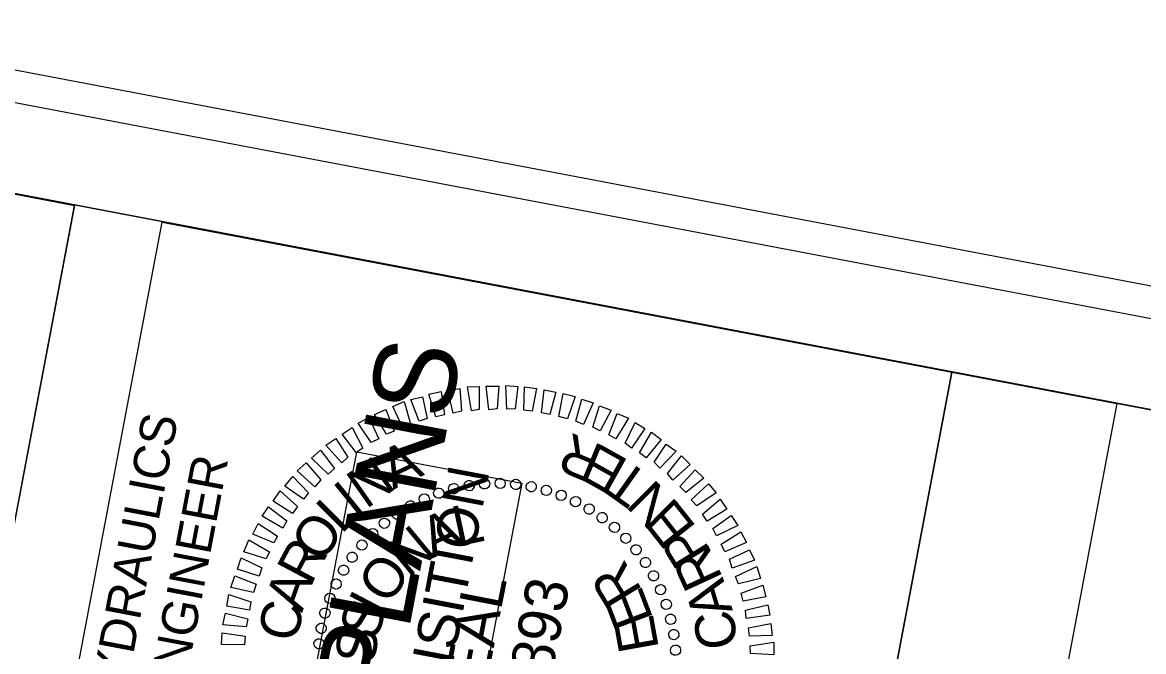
# Model space of a CAD drawing. Extents: x 1615685 to 1617075, y 899072 to 901363.
# Drawn here: x 1616035.7 to 1616192.6, y 901079 to 901167 of the extents above; entities that cross this region are included whole.
import ezdxf

# ---------------------------------------------------------------- set-up
doc = ezdxf.new("R2010")
doc.units = 0
for name, color, linetype in [('Default', 7, 'Continuous'), ('Exist Plan Preparation Drainage Flow Arrows', 7, 'Continuous'), ('Exist Plan Preparation Drainage Notes Label', 7, 'Continuous'), ('Exist Structure Minor Pipes CMP 15 Inch Text', 7, 'Continuous'), ('Exist Structure Minor Pipes RCP 15 Inch Text', 7, 'Continuous'), ('Prop Drainage Structure Drop Inlet Grate 840 16 CELL', 7, 'Continuous'), ('Scratch_Level_8', 7, 'Continuous')]:
    doc.layers.add(name, color=color, linetype=linetype)

msp = doc.modelspace()

# ---------------------------------------------------------------- linework, layer by layer
at = {"layer": 'Default'}
for p, q in [((1616096.14, 901101.79), (1616096.14, 901101.79)), ((1616098.26, 901102.24), (1616098.26, 901102.24)), ((1616100.4, 901102.48), (1616100.4, 901102.48)), ((1616102.64, 901102.51), (1616102.64, 901102.51)), ((1616104.81, 901102.39), (1616104.81, 901102.39)), ((1616107, 901102.12), (1616107, 901102.12)), ((1616109.14, 901101.6), (1616109.14, 901101.6)), ((1616091.98, 901100.35), (1616091.98, 901100.35)), ((1616094.03, 901101.18), (1616094.03, 901101.18)), ((1616111.14, 901100.9), (1616111.14, 901100.9)), ((1616113.21, 901099.99), (1616113.21, 901099.99)), ((1616088.11, 901098.26), (1616088.11, 901098.26)), ((1616090.03, 901099.46), (1616090.03, 901099.46)), ((1616115.09, 901098.96), (1616115.09, 901098.96)), ((1616086.39, 901097.01), (1616086.39, 901097.01)), ((1616116.9, 901097.79), (1616116.9, 901097.79)), ((1616084.72, 901095.5), (1616084.72, 901095.5)), ((1616118.63, 901096.44), (1616118.63, 901096.44)), ((1616083.25, 901093.96), (1616083.25, 901093.96)), ((1616120.21, 901094.91), (1616120.21, 901094.91)), ((1616081.9, 901092.23), (1616081.9, 901092.23)), ((1616121.67, 901093.25), (1616121.67, 901093.25)), ((1616080.68, 901090.43), (1616080.68, 901090.43)), ((1616122.97, 901091.52), (1616122.97, 901091.52)), ((1616124.12, 901089.61), (1616124.12, 901089.61)), ((1616079.64, 901088.49), (1616079.64, 901088.49)), ((1616125.02, 901087.65), (1616125.02, 901087.65)), ((1616078.79, 901086.47), (1616078.79, 901086.47)), ((1616125.9, 901085.65), (1616125.9, 901085.65)), ((1616078.08, 901084.42), (1616078.08, 901084.42)), ((1616126.5, 901083.49), (1616126.5, 901083.49)), ((1616077.51, 901082.29), (1616077.51, 901082.29)), ((1616126.95, 901081.37), (1616126.95, 901081.37)), ((1616077.24, 901080.1), (1616077.24, 901080.1)), ((1616127.2, 901079.23), (1616127.2, 901079.23))]:
    msp.add_line(p, q, dxfattribs=at)
for points in [[(1616096, 901112.36), (1616095.25, 901115.56), (1616096.94, 901115.84), (1616097.18, 901112.64)], [(1616098.57, 901112.72), (1616098, 901116.04), (1616099.63, 901116.08), (1616099.62, 901112.87)], [(1616100.99, 901112.86), (1616100.61, 901116.15), (1616102.4, 901116.15), (1616102.14, 901113)], [(1616103.5, 901112.93), (1616103.38, 901116.22), (1616105.04, 901116.1), (1616104.68, 901112.96)], [(1616105.87, 901112.78), (1616106, 901116.06), (1616107.68, 901115.84), (1616107.06, 901112.65)], [(1616108.34, 901112.4), (1616108.72, 901115.64), (1616110.38, 901115.31), (1616109.52, 901112.17)], [(1616088.93, 901110.32), (1616087.53, 901113.29), (1616089.14, 901114), (1616090.01, 901110.88)], [(1616091.25, 901111.24), (1616090.06, 901114.28), (1616091.72, 901114.67), (1616092.35, 901111.64)], [(1616093.56, 901111.86), (1616092.6, 901115.01), (1616094.3, 901115.39), (1616094.79, 901112.13)], [(1616110.79, 901111.92), (1616111.41, 901115.11), (1616113.06, 901114.69), (1616112, 901111.58)], [(1616113.16, 901111.26), (1616114.02, 901114.35), (1616115.6, 901113.84), (1616114.24, 901110.79)], [(1616086.67, 901109.44), (1616084.97, 901112.21), (1616086.58, 901112.87), (1616087.72, 901109.84)], [(1616115.55, 901110.43), (1616116.48, 901113.41), (1616118.09, 901112.79), (1616116.56, 901109.88)], [(1616117.78, 901109.34), (1616118.97, 901112.32), (1616120.52, 901111.66), (1616118.74, 901108.79)], [(1616084.51, 901108.28), (1616082.69, 901110.98), (1616084.17, 901111.76), (1616085.58, 901108.78)], [(1616120.05, 901108.18), (1616121.48, 901111.06), (1616122.84, 901110.24), (1616120.94, 901107.5)], [(1616082.4, 901106.86), (1616080.46, 901109.42), (1616081.86, 901110.37), (1616083.34, 901107.49)], [(1616122.08, 901106.82), (1616123.76, 901109.7), (1616125.09, 901108.68), (1616123.01, 901106.13)], [(1616080.39, 901105.41), (1616078.17, 901107.88), (1616079.58, 901108.83), (1616081.26, 901106.21)], [(1616124.11, 901105.51), (1616125.83, 901108.03), (1616127.21, 901107.04), (1616124.92, 901104.69)], [(1616078.5, 901103.85), (1616076.14, 901106.09), (1616077.43, 901107.21), (1616079.37, 901104.64)], [(1616125.99, 901103.92), (1616127.95, 901106.39), (1616129.19, 901105.18), (1616126.73, 901103.01)], [(1616076.63, 901102.07), (1616074.17, 901104.33), (1616075.4, 901105.42), (1616077.48, 901103.03)], [(1616075.02, 901100.35), (1616072.42, 901102.18), (1616073.55, 901103.54), (1616075.75, 901101.22)], [(1616127.73, 901102.1), (1616129.86, 901104.44), (1616131.07, 901103.29), (1616128.54, 901101.28)], [(1616073.51, 901098.35), (1616070.79, 901100.05), (1616071.78, 901101.49), (1616074.21, 901099.33)], [(1616129.31, 901100.27), (1616131.73, 901102.5), (1616132.8, 901101.22), (1616130.11, 901099.4)], [(1616130.9, 901098.23), (1616133.35, 901100.35), (1616134.29, 901098.94), (1616131.53, 901097.29)], [(1616072.14, 901096.27), (1616069.26, 901097.95), (1616070.12, 901099.26), (1616072.7, 901097.33)], [(1616070.87, 901094.23), (1616067.96, 901095.46), (1616068.7, 901096.94), (1616071.42, 901095.19)], [(1616132.35, 901096.26), (1616134.89, 901098.06), (1616135.84, 901096.65), (1616132.86, 901095.24)], [(1616133.5, 901094.05), (1616136.28, 901095.8), (1616137.05, 901094.28), (1616134, 901092.98)], [(1616069.83, 901091.99), (1616066.71, 901093), (1616067.39, 901094.65), (1616070.27, 901092.97)], [(1616068.85, 901089.58), (1616065.78, 901090.58), (1616066.3, 901092.16), (1616069.22, 901090.73)], [(1616134.66, 901091.94), (1616137.47, 901093.28), (1616138.16, 901091.82), (1616135.03, 901090.7)], [(1616135.52, 901089.53), (1616138.49, 901090.94), (1616139.03, 901089.25), (1616135.94, 901088.53)], [(1616068.05, 901087.29), (1616064.87, 901088.01), (1616065.45, 901089.63), (1616068.42, 901088.44)], [(1616136.29, 901087.19), (1616139.36, 901088.32), (1616139.75, 901086.67), (1616136.58, 901086.07)], [(1616067.46, 901084.81), (1616064.31, 901085.37), (1616064.58, 901087), (1616067.69, 901085.98)], [(1616067.01, 901082.5), (1616063.75, 901082.78), (1616064.12, 901084.39), (1616067.23, 901083.63)], [(1616136.9, 901084.83), (1616140.05, 901085.59), (1616140.32, 901084.11), (1616137.02, 901083.64)], [(1616137.33, 901082.35), (1616140.45, 901082.97), (1616140.64, 901081.3), (1616137.46, 901081.21)], [(1616066.78, 901080), (1616063.57, 901080.01), (1616063.64, 901081.68), (1616066.86, 901081.2)], [(1616137.56, 901079.86), (1616140.86, 901080.34), (1616140.88, 901078.6), (1616137.6, 901078.78)]]:
    msp.add_lwpolyline(points, close=True, dxfattribs=at)
for centre, major_axis in [((1616098.22, 901102.24), (-0.112, 0.71)), ((1616100.39, 901102.49), (-0.05, 0.718)), ((1616102.57, 901102.55), (0.013, 0.719)), ((1616104.75, 901102.41), (0.075, 0.715)), ((1616093.98, 901101.19), (-0.234, 0.68)), ((1616096.07, 901101.81), (-0.174, 0.698)), ((1616106.92, 901102.09), (0.138, 0.706)), ((1616109.04, 901101.58), (0.199, 0.691)), ((1616111.11, 901100.88), (0.258, 0.671)), ((1616089.99, 901099.41), (-0.348, 0.629)), ((1616091.94, 901100.39), (-0.292, 0.657)), ((1616113.12, 901100.01), (0.316, 0.646)), ((1616115.04, 901098.97), (0.371, 0.616)), ((1616088.12, 901098.27), (-0.402, 0.596)), ((1616116.86, 901097.76), (0.423, 0.582)), ((1616086.37, 901096.97), (-0.452, 0.559)), ((1616118.57, 901096.4), (0.472, 0.543)), ((1616084.73, 901095.53), (-0.499, 0.518)), ((1616120.16, 901094.89), (0.518, 0.499)), ((1616083.22, 901093.94), (-0.543, 0.472)), ((1616121.6, 901093.26), (0.559, 0.452)), ((1616081.86, 901092.23), (-0.582, 0.423)), ((1616122.9, 901091.5), (0.596, 0.402)), ((1616080.66, 901090.41), (-0.616, 0.371)), ((1616124.04, 901089.63), (0.629, 0.348)), ((1616079.61, 901088.49), (-0.646, 0.316)), ((1616078.74, 901086.48), (-0.671, 0.258)), ((1616125.02, 901087.68), (0.657, 0.292)), ((1616125.82, 901085.64), (0.68, 0.234)), ((1616078.04, 901084.41), (-0.691, 0.199)), ((1616126.44, 901083.55), (0.698, 0.174)), ((1616077.53, 901082.29), (-0.706, 0.138)), ((1616126.87, 901081.41), (0.71, 0.112)), ((1616077.21, 901080.12), (-0.715, 0.075)), ((1616127.12, 901079.23), (0.718, 0.05))]:
    msp.add_ellipse(centre, major_axis=major_axis, ratio=0.999708, dxfattribs=at)
at = {"layer": 'Exist Plan Preparation Drainage Flow Arrows'}
msp.add_lwpolyline([(1616744, 899325.3), (1617054.75, 900962.05), (1616018.28, 901158.86), (1615707.51, 899522.1)], close=True, dxfattribs=at)
at = {"layer": 'Exist Plan Preparation Drainage Notes Label'}
msp.add_lwpolyline([(1616761.22, 899308.8), (1617075.25, 900962.75), (1615999.47, 901167.01), (1615685.44, 899513.06)], close=True, dxfattribs=at)
at = {"layer": 'Exist Structure Minor Pipes CMP 15 Inch Text'}
for p, q in [((1616128.49, 900921.6), (1616165.81, 901118.12)), ((1616128.49, 900921.6), (1616165.81, 901118.12)), ((1616165.82, 901118.12), (1616188.91, 901113.74)), ((1616165.82, 901118.12), (1616188.91, 901113.74)), ((1616188.9, 901113.74), (1616151.58, 900917.21)), ((1616188.9, 901113.74), (1616151.58, 900917.21))]:
    msp.add_line(p, q, dxfattribs=at)
at = {"layer": 'Exist Structure Minor Pipes RCP 15 Inch Text'}
msp.add_lwpolyline([(1616078.19, 900958.16), (1616055.11, 900962.54), (1616082.53, 901106.96), (1616105.61, 901102.58)], close=True, dxfattribs=at)
at = {"layer": 'Prop Drainage Structure Drop Inlet Grate 840 16 CELL'}
msp.add_lwpolyline([(1616181.54, 900871.6), (1616226.17, 901106.67), (1616018.4, 901146.15), (1615973.76, 900911.05)], close=True, dxfattribs=at)
at = {"layer": 'Scratch_Level_8'}
msp.add_line((1616005.71, 900944.9), (1616043, 901141.43), dxfattribs=at)
msp.add_line((1616005.71, 900944.9), (1616043, 901141.43), dxfattribs=at)
for points in [[(1616018.4, 901146.14), (1615738.59, 899672.43), (1616770.16, 899476.57), (1617049.96, 900950.25)], [(1615981.06, 900949.58), (1616018.4, 901146.14), (1616043, 901141.43), (1616005.71, 900944.9)], [(1616036.64, 901040.86), (1616055.28, 901139.09), (1616165.82, 901118.12), (1616147.18, 901019.87)], [(1616770.16, 899476.57), (1615738.61, 899672.4), (1615981.06, 900949.58), (1616128.49, 900921.6), (1616165.82, 901118.12), (1617049.96, 900950.25)]]:
    msp.add_lwpolyline(points, close=True, dxfattribs=at)

# ---------------------------------------------------------------- texts
at = {"layer": 'Default'}
for s, height, rotation, p in [('R', 5.6, 157.5754, (1616117.36, 901107.66)), ('A', 5.6, 25.4827, (1616087.58, 901101.64)), ('E', 5.6, 150.9271, (1616120.75, 901105.7)), ('N', 5.6, 35.028, (1616083.78, 901098.88)), ('T', 5.6, 144.5264, (1616123.78, 901103.45)), ('N', 5.6, 134.9812, (1616127.78, 901099.51)), ('I', 5.6, 39.0269, (1616082.34, 901097.55)), ('L', 5.6, 45.0066, (1616080.36, 901095.37)), ('E', 5.6, 128.3329, (1616130.16, 901096.4)), ('A', 5.6, 24.8152, (1616093.14, 901092.08)), ('L', 5.6, 12.1473, (1616096.56, 901093.71)), ('O', 5.6, 55.2204, (1616077.54, 901091.22)), ('N', 5.6, 39.731, (1616089.7, 901089.26)), ('P', 5.6, 121.6846, (1616132.15, 901093.04)), ('R', 5.6, 62.1659, (1616076.06, 901088.14)), ('R', 5.6, 114.7392, (1616133.81, 901089.3)), ('O', 5.6, 55.6419, (1616086.95, 901085.39)), ('R', 5.6, 121.432, (1616122.57, 901087.52)), ('A', 5.6, 70.2007, (1616074.83, 901084.38)), ('SEAL', 5.992, 78.9784, (1616099.61, 901068.97)), ('045893', 5.994, 78.9784, (1616107.24, 901062.37)), ('A', 5.6, 106.7043, (1616135.15, 901084.76)), ('I', 5.6, 62.3029, (1616086.14, 901083.57)), ('E', 5.6, 110.8278, (1616124.06, 901083.6)), ('C', 5.6, 78.8299, (1616074.11, 901080.2)), ('S', 5.6, 73.165, (1616085.29, 901080.44)), ('E', 5.6, 100.2236, (1616124.81, 901079.47)), ('C', 5.6, 98.0752, (1616135.86, 901079.73)), ('S', 5.6, 84.0272, (1616085.04, 901077.2))]:
    msp.add_text(s, height=height, rotation=rotation, dxfattribs=at).set_placement(p)
at = {"layer": 'Exist Structure Minor Pipes RCP 15 Inch Text'}
for s, height, p in [('INCOMPLETE PLANS', 11.52, (1616068.37, 900969.13)), ('DO NOT USE FOR R/W ACQUISITION', 5.76, (1616075.8, 900971.03))]:
    msp.add_text(s, height=height, rotation=79.2494, dxfattribs=at).set_placement(p)
at = {"layer": 'Scratch_Level_8'}
for s, p in [('HYDRAULICS', (1616049.47, 901069.43)), ('ENGINEER', (1616058, 901071.64))]:
    msp.add_text(s, height=5, rotation=79.2494, dxfattribs=at).set_placement(p)

doc.saveas('drawing.dxf')
